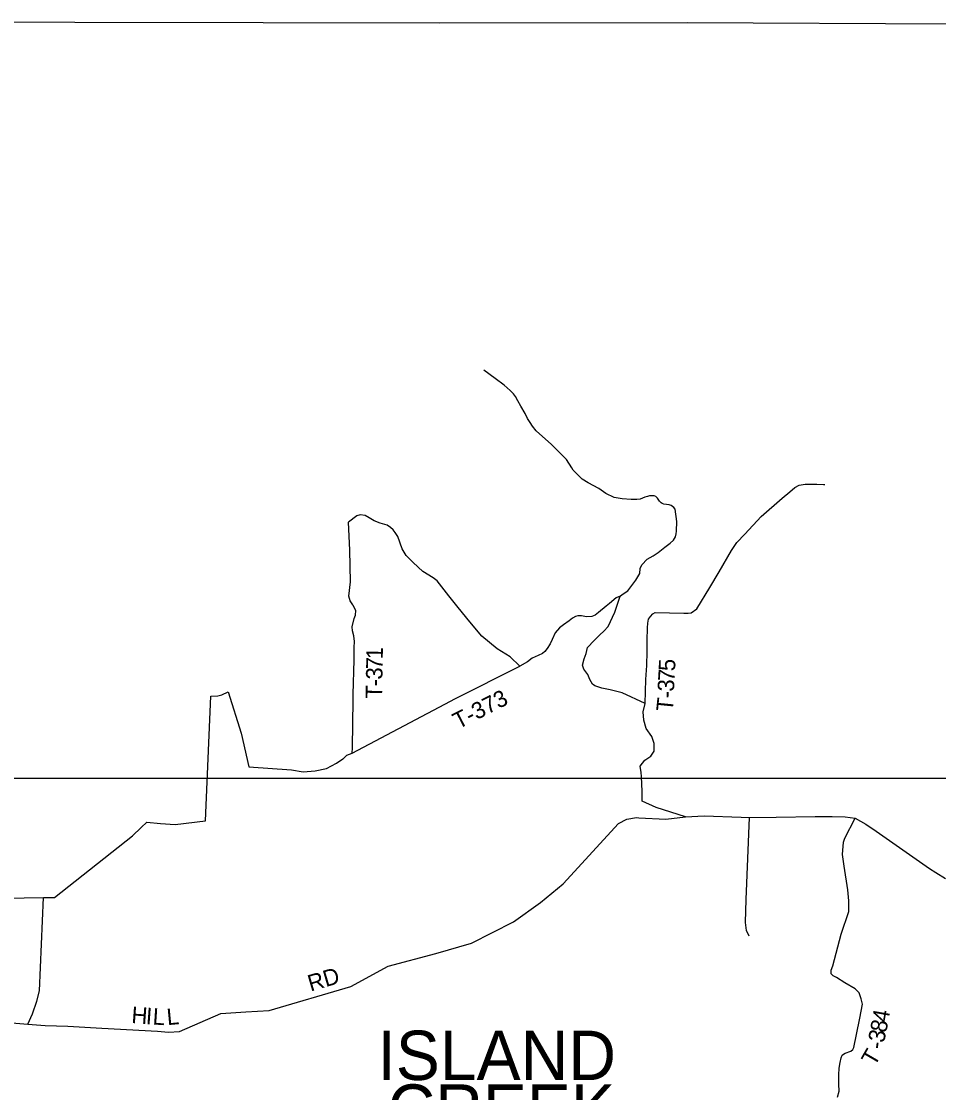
# Model space of a CAD drawing. Extents: x 2402298 to 2498138, y 789485 to 950881.
# Drawn here: x 2459820 to 2476534, y 883995 to 903520 of the extents above; entities that cross this region are included whole.
import ezdxf

# ---------------------------------------------------------------- set-up
doc = ezdxf.new("R2010")
doc.units = 0
for name, color, linetype in [('GM_X_County_Road', 7, 'Continuous'), ('GM_X_County_Road_Text', 7, 'Continuous'), ('GM_X_Township', 7, 'Continuous'), ('GM_X_Township_Road', 7, 'Continuous'), ('GM_X_Township_Road_Text', 7, 'Continuous'), ('GM_X_Township_Text', 7, 'Continuous'), ('SH_Text', 7, 'Continuous')]:
    doc.layers.add(name, color=color, linetype=linetype)

msp = doc.modelspace()

# ---------------------------------------------------------------- linework, layer by layer
at = {"layer": 'GM_X_County_Road'}
for points in [[(2463907, 885464), (2464335, 885490), (2465826, 885931), (2466505, 886301), (2467375, 886533), (2468023, 886718), (2468790, 887108), (2469280, 887458), (2469691, 887803), (2470703, 888902), (2470851, 888978), (2471030, 889008), (2471073, 889006)], [(2471073, 889006), (2471561, 888978), (2471921, 889020), (2472261, 889039), (2472938, 889016)], [(2472938, 889016), (2473090, 889010), (2473576, 889014), (2474287, 889029), (2474593, 889025), (2474831, 889020), (2475017, 888995)], [(2475017, 888995), (2475210, 888887), (2475397, 888760), (2476004, 888334), (2476370, 888082), (2476487, 888005), (2476659, 887898)], [(2457627, 884923), (2458014, 885046), (2458222, 885097), (2458464, 885167), (2459267, 885275), (2459570, 885275), (2459938, 885242), (2460250, 885215), (2460668, 885203), (2461287, 885172), (2462299, 885114), (2462503, 885097), (2462703, 885107), (2463453, 885436), (2463907, 885464)]]:
    msp.add_lwpolyline(points, dxfattribs=at)
at = {"layer": 'GM_X_Township'}
msp.add_lwpolyline([(2455910, 903520), (2460796, 903505), (2464223, 903502), (2467432, 903495), (2471955, 903500), (2476767, 903474)], dxfattribs=at)
at = {"layer": 'GM_X_Township_Road'}
msp.add_line((2465848, 890180), (2465854, 890277), dxfattribs=at)
for points in [[(2471184, 891088), (2470769, 891281), (2470552, 891337), (2470396, 891364), (2470272, 891407), (2470226, 891442), (2470176, 891524), (2470140, 891614), (2470071, 891712), (2470043, 891789), (2470076, 891899), (2470113, 891998), (2470136, 892106), (2470258, 892238), (2470360, 892341), (2470435, 892405), (2470514, 892490), (2470636, 892754), (2470729, 893042), (2470765, 893076), (2470870, 893140), (2470923, 893211), (2471017, 893336), (2471088, 893455), (2471098, 893546), (2471129, 893612), (2471226, 893717), (2471332, 893778), (2471422, 893839), (2471546, 893939), (2471641, 894007), (2471704, 894063), (2471738, 894125), (2471750, 894180), (2471758, 894226), (2471764, 894406), (2471731, 894628), (2471709, 894657), (2471683, 894681), (2471658, 894694), (2471624, 894708), (2471528, 894719), (2471497, 894730), (2471477, 894747), (2471449, 894776), (2471412, 894831), (2471381, 894859), (2471351, 894871), (2471314, 894875), (2471268, 894871), (2471227, 894863), (2471179, 894847), (2471094, 894814), (2471035, 894803), (2470929, 894803), (2470766, 894816), (2470621, 894843), (2470472, 894917), (2470345, 895004), (2470148, 895110), (2470040, 895177), (2469874, 895339), (2469852, 895385), (2469753, 895532), (2469508, 895777), (2469473, 895816), (2469371, 895907), (2469200, 896060), (2469136, 896142), (2469091, 896209), (2469045, 896285), (2468998, 896373), (2468923, 896510), (2468868, 896607), (2468822, 896681), (2468790, 896733), (2468728, 896795), (2468619, 896888), (2468456, 897014), (2468246, 897163)], [(2471112, 889829), (2471093, 889948), (2471183, 890053), (2471292, 890125), (2471351, 890221), (2471348, 890356), (2471306, 890483), (2471207, 890633), (2471162, 890785), (2471153, 890935), (2471184, 891088), (2471197, 891523), (2471216, 891781), (2471223, 892034), (2471226, 892234), (2471230, 892465), (2471237, 892550), (2471250, 892622), (2471283, 892674), (2471328, 892724), (2471370, 892745), (2471890, 892736), (2471969, 892735), (2472026, 892743), (2472127, 892810), (2472367, 893199), (2472534, 893487), (2472759, 893878), (2472855, 894023), (2473001, 894172), (2473301, 894495), (2473685, 894829), (2473825, 894947), (2473915, 895022), (2473996, 895067), (2474105, 895084), (2474313, 895088), (2474437, 895079), (2474463, 895078)], [(2468905, 891766), (2468726, 891935), (2468488, 892082), (2468211, 892317), (2467993, 892575), (2467782, 892837), (2467610, 893052), (2467398, 893321), (2467324, 893378), (2467137, 893495), (2466958, 893655), (2466833, 893783), (2466758, 893904), (2466679, 894131), (2466629, 894205), (2466592, 894250), (2466544, 894297), (2466486, 894338), (2466355, 894377), (2466249, 894417), (2466160, 894471), (2466083, 894514), (2465994, 894525), (2465933, 894506), (2465780, 894391)], [(2465866, 891148), (2465868, 891254), (2465882, 891883), (2465881, 892106), (2465888, 892217), (2465879, 892319), (2465853, 892410), (2465846, 892484), (2465881, 892634), (2465905, 892695), (2465917, 892782), (2465867, 892874), (2465860, 892886), (2465813, 892956), (2465786, 893043), (2465818, 893307), (2465804, 893883), (2465780, 894391)], [(2470729, 893042), (2470660, 893011), (2470536, 892911), (2470476, 892859), (2470339, 892746), (2470277, 892697), (2470214, 892671), (2470119, 892668), (2470028, 892685), (2469961, 892685), (2469917, 892673), (2469863, 892644), (2469803, 892592), (2469700, 892521), (2469627, 892469), (2469546, 892377), (2469492, 892255), (2469457, 892173), (2469400, 892090), (2469361, 892036), (2469315, 891999), (2469238, 891965), (2469126, 891911), (2469043, 891847), (2468905, 891766)], [(2467539, 891074), (2467732, 891176), (2468905, 891766)], [(2459168, 887531), (2460220, 887549), (2460420, 887553), (2461846, 888677), (2462001, 888829), (2462103, 888925), (2462353, 888902), (2462621, 888884), (2463175, 888947), (2463274, 891219), (2463400, 891226), (2463471, 891245), (2463588, 891298), (2463825, 890544), (2463962, 889935), (2464744, 889881), (2464952, 889841), (2465170, 889857), (2465381, 889902), (2465560, 889998), (2465680, 890081), (2465688, 890087), (2465700, 890099)], [(2465854, 890277), (2465854, 890286), (2465866, 891148)], [(2465700, 890099), (2465749, 890146), (2465848, 890180), (2467539, 891074)], [(2471921, 889020), (2471390, 889193), (2471134, 889305), (2471134, 889485), (2471123, 889757), (2471112, 889829)], [(2473083, 886847), (2473032, 886947), (2473015, 887097), (2473029, 887512), (2473090, 889010)], [(2474577, 886205), (2474578, 886226), (2474605, 886305), (2474757, 886884), (2474900, 887297), (2474900, 887493), (2474878, 887689), (2474811, 888120), (2474783, 888333), (2474803, 888561), (2474828, 888632), (2475017, 888995)], [(2459938, 885242), (2460021, 885429), (2460100, 885659), (2460152, 885849), (2460220, 887549)], [(2474694, 883910), (2474720, 884023), (2474718, 884151), (2474717, 884317), (2474721, 884441), (2474738, 884541), (2474759, 884631), (2474775, 884675), (2474799, 884696), (2474832, 884716), (2474933, 884748), (2474970, 884779), (2474990, 884815), (2475040, 885055), (2475102, 885350), (2475146, 885606), (2475123, 885704), (2475084, 885816), (2475015, 885888), (2474826, 885995), (2474676, 886090), (2474612, 886125), (2474576, 886160), (2474577, 886205)]]:
    msp.add_lwpolyline(points, dxfattribs=at)
at = {"layer": 'SH_Text'}
msp.add_lwpolyline([(2448187, 889729), (2496836, 889729), (2496836, 859271), (2448187, 859271)], close=True, dxfattribs=at)

# ---------------------------------------------------------------- texts
at = {"layer": 'GM_X_County_Road_Text'}
for s, rotation, p in [('RD', 16.4177, (2465089, 885835)), ('H', 356.019, (2461818, 885264)), ('I', 356.0226, (2462081, 885245)), ('L', 356.2885, (2462205, 885237)), ('L', 5.4297, (2462481, 885223))]:
    msp.add_text(s, height=300, rotation=rotation, dxfattribs=at).set_placement(p)
at = {"layer": 'GM_X_Township_Road_Text'}
for s, rotation, p in [('7', 88.9591, (2466401, 891706)), ('1', 88.7978, (2466404, 891891)), ('3', 89.0164, (2466398, 891521)), ('5', 87.2987, (2471731, 891672)), ('-', 89.0326, (2466396, 891398)), ('7', 86.5373, (2471720, 891483)), ('T', 89.0228, (2466392, 891174)), ('T-373', 26.9405, (2467780, 890613)), ('3', 87.9752, (2471713, 891300)), ('T', 84.3295, (2471686, 890931)), ('-', 88.4418, (2471710, 891178)), ('4', 79.9925, (2475614, 885261)), ('8', 78.7514, (2475577, 885073)), ('3', 78.3461, (2475539, 884890)), ('-', 81.9377, (2475522, 884773)), ('T', 59.8697, (2475369, 884460))]:
    msp.add_text(s, height=300, rotation=rotation, dxfattribs=at).set_placement(p)
at = {"layer": 'GM_X_Township_Text'}
for s, p in [('ISLAND', (2466308, 884224)), ('CREEK', (2466491, 883244))]:
    msp.add_text(s, height=900, rotation=0, dxfattribs=at).set_placement(p)

doc.saveas('drawing.dxf')
